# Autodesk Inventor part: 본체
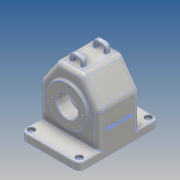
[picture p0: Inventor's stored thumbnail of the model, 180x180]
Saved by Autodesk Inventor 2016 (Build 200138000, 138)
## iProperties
Created: 2016-12
Part Number: 본체
Material: 알루미늄 6061
Document SubType Name: Modeling
Designer: Administrator
Density: 2.7 g/cm^3
Appearance: 알루미늄 - 평지
Mass: 1062.96 g
Surface Area: 1138.83 cm^2
Volume: 393.688 cm^3
Author: Administrator
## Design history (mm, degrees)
sketch "스케치1"
  geometry: L1 (45, -75)-(-45, -75); L2 (-55, -65)-(-55, 65); L3 (-45, 75)-(45, 75); L4 (55, 65)-(55, -65); L5 (55, -75)-(-55, 75); L6 (-55, -75)-(55, 75); A1 r 10 centre (-45, 65) between (-45, 75) and (-55, 65); A2 r 10 centre (45, 65) between (55, 65) and (45, 75); A3 r 10 centre (45, -65) between (45, -75) and (55, -65); A4 r 10 centre (-45, -65) between (-55, -65) and (-45, -75); 1 further point
  constraints: 12 end point, 8 point on circle, 8 point on line, 8 tangent, 4 centre point, 3 equal radius, 2 midpoint, 2 parallel, 1 horizontal, 1 perpendicular
  dimensions: "d0" = 110 distance of L5.end L6.end; "d1" = 150 distance of L6.start L5.end; "d2" = 10 radius of A1
extrude "돌출1" new body sketch "스케치1" distance "d3" = 15; taper "d4" = 0 deg
node "작업 평면1"
sketch "스케치2"
  geometry: L1 (55, 0)-(55, 15) reference; L2 (-55, 0)-(-55, 15) reference; L3 (45, 15)-(-45, 15) reference; L4 (55, 15)-(55, 80); L5 (55, 80)-(23.491, 125); L6 (23.491, 125)-(-23.491, 125); L7 (-23.491, 125)-(-55, 80); L8 (-55, 80)-(-55, 15); L9 (-45, 0)-(45, 0) reference; L10 (0, 125)-(0, 0)
  constraints: 12 end point, 2 perpendicular, 1 midpoint, 1 parallel, 1 vertical, 1 other
  dimensions: "d6" = 80 distance from line of L9 L4.end; "d7" = 125 distance between parallel lines of L9 L6; "d8" = 35 deg angle of L8 L7
extrude "돌출2" join sketch "스케치2" distance "d10" = 77; taper "d11" = 0 deg
node "작업 평면2"
sketch "스케치6"
  geometry: L1 (-55, 15)-(-55, 80) reference; L2 (-55, 80)-(-23.491, 125) reference; L3 (-23.491, 125)-(23.491, 125) reference; L4 (23.491, 125)-(55, 80) reference; L5 (55, 80)-(55, 15) reference; L6 (55, 0)-(55, 15) reference; L7 (-45, 0)-(45, 0) reference; L8 (-55, 0)-(-45, 0) reference; L9 (-55, 0)-(-55, 15) reference; L10 (45, 0)-(55, 0) reference; L11 (20.888, 120)-(-20.888, 120); L12 (-20.888, 120)-(-50, 78.424); L13 (-50, 78.424)-(-50, 15); L14 (-50, 15)-(-50, 0); L15 (50, 0)-(50, 15); L16 (50, 15)-(50, 78.424); L17 (50, 78.424)-(20.888, 120); L18 (50, 0)-(-50, 0); 1 further point
  constraints: 16 end point, 2 midpoint, 1 collinear, 3 other
  dimensions: "d30" = 5 distance between parallel lines of L3 L11
extrude "돌출3" cut sketch "스케치6" distance "d31" = 67; taper "d32" = 0 deg
sketch "스케치4"
  geometry: L1 (-43.5, 65)-(48.5, 65); L2 (-38.5, 102.5)-(-43.5, 102.5); L3 (-43.5, 102.5)-(-43.5, 65); L4 (38.5, 80)-(38.5, 125) reference; L5 (38.5, 96)-(48.5, 96); L6 (48.5, 96)-(48.5, 65); L7 (-38.5, 102.5)-(-38.5, 65); L8 (38.5, 96)-(38.5, 65); L9 (38.5, 15)-(38.5, 80) reference; L10 (-38.5, 80)-(-38.5, 125) reference; 1 further point
  constraints: 14 end point, 4 point on line, 3 horizontal, 3 perpendicular, 1 vertical alignment
  dimensions: "d13" = 65 vertical distance of L1.start point (0, 0); "d14" = 75 diameter of L2 L1; "d15" = 62 diameter of L5 L1; "d16" = 5 distance of L2.start L2.end; "d17" = 87 distance from line of L10 L5.end
revolve "회전1" sketch "스케치4" stored, may be unused: angle "d18" = 90 deg
sketch "스케치7"
  geometry: L1 (-33.5, 120)-(-33.5, 78.424) reference; L2 (-33.5, 78.424)-(-33.5, 0) reference; L3 (-33.5, 65)-(33.5, 65); L4 (33.5, 0)-(33.5, 78.424) reference; L5 (-19.5, 92)-(-19.5, 65); L6 (-43.5, 27.5)-(-43.5, 102.5) reference; L7 (-19.5, 92)-(-33.5, 106); 1 further point
  constraints: 6 end point, 4 point on line, 2 perpendicular
  dimensions: "d33" = 54 diameter of L5.start L3; "d34" = 130 diameter of point (0, 0) L3; "d36" = 24 distance between parallel lines of L6 L5; "d37" = 45 deg angle of L5 L7
revolve "회전3" sketch "스케치7" stored, may be unused: angle "d38" = 90 deg
hole "구멍1" diameter "d41" = 40; stored, may be unused: countersink angle "d45" = 90 deg, drill point angle "d47" = 118 deg; dims "d39" = 10, "d40" = 10, "d42" = 6, "d43" = 4, "d44" = 2, "d46" = 8
chamfer "모따기1" distance "d48" = 1; stored, may be unused: second distance "d49" = 2, angle "d50" = 45 deg
fillet "모깎기1" dims "d51" = 3
fillet "모깎기2" dims "d52" = 3
node "작업 평면3"
sketch "스케치8"
  geometry: L1 (12.5, 125)-(12.5, 132); L2 (4.5, 140)-(-4.5, 140); L3 (-12.5, 132)-(-12.5, 125); L4 (23.491, 125)-(-23.491, 125) reference; L5 (23.491, 125)-(-23.491, 125) reference; L6 (-45, 0)-(45, 0) reference; L7 (0, 125)-(0, 140); L8 (-7.5, 125)-(-7.5, 132); L9 (-4.5, 135)-(4.5, 135); L10 (7.5, 132)-(7.5, 125); L11 (7.5, 125)-(12.5, 125); L12 (-7.5, 125)-(-12.5, 125); L13 (47, 0)-(47, 77.478) reference; A1 r 8 centre (4.5, 132) between (12.5, 132) and (4.5, 140); A2 r 8 centre (-4.5, 132) between (-4.5, 140) and (-12.5, 132); A3 r 3 centre (-4.5, 132) between (-4.5, 135) and (-7.5, 132); A4 r 3 centre (4.5, 132) between (7.5, 132) and (4.5, 135); 3 further points
  constraints: 18 end point, 8 point on circle, 8 point on line, 5 perpendicular, 4 centre point, 4 tangent, 2 midpoint, 2 vertical, 1 collinear, 1 equal radius, 5 other
  dimensions: "d54" = 25 distance of point (12.5, 140) point (-12.5, 140); "d55" = 140 distance between parallel lines of L6 L2; "d56" = 8 radius of A1; "d57" = 5 distance between parallel lines of L2 L9
extrude "돌출4" join sketch "스케치8" distance "d60" = 8; taper "d61" = 0 deg
fillet "모깎기3" dims "d62" = 1
fillet "모깎기4" dims "d63" = 1
sketch "스케치9"
  geometry: C1 r 37.5 at (0, 0) reference; C2 r 21 at (0, 0) reference; A1 r 29 centre (0, 0) between (0, 29) and (0, -29); 3 further points
  constraints: 4 point on circle, 2 horizontal alignment, 2 vertical alignment, 1 centre point, 1 coincident
  dimensions: "d64" = 58 diameter of A1
hole "구멍2" sketch "스케치9" at (0, 29), (0, -29), (-29, 0), (29, 0) diameter "d65" = 2.459; stored, may be unused: countersink angle "d69" = 90 deg, drill point angle "d71" = 118 deg; dims "d66" = 6, "d67" = 4, "d68" = 2, "d70" = 8
sketch "스케치10"
  geometry: C1 r 31 at (0, 0) reference; C2 r 21 at (0, 0) reference; A1 r 26 centre (0, 0) between (-26, 0) and (26, 0); 3 further points
  constraints: 4 point on circle, 2 horizontal alignment, 2 vertical alignment, 1 centre point, 1 coincident
  dimensions: "d72" = 52 diameter of A1
hole "구멍3" sketch "스케치10" at (-26, 0), (26, 0), (0, -26), (0, 26) diameter "d73" = 2.459; stored, may be unused: countersink angle "d77" = 90 deg, drill point angle "d79" = 118 deg; dims "d74" = 6, "d75" = 4, "d76" = 2, "d78" = 8
sketch "스케치11"
  geometry: A1 r 10 centre (-45, -65) between (-55, -65) and (-45, -75) reference; A2 r 10 centre (45, -65) between (45, -75) and (55, -65) reference; A3 r 10 centre (-45, 65) between (-45, 75) and (-55, 65) reference; A4 r 10 centre (45, 65) between (55, 65) and (45, 75) reference; 5 further points
  constraints: 4 coincident
hole "구멍4" sketch "스케치11" at (-45, -65), (45, -65), (-45, 65), (45, 65) diameter "d80" = 5; stored, may be unused: countersink angle "d84" = 90 deg, drill point angle "d86" = 118 deg; dims "d81" = 6, "d82" = 12, "d83" = 5, "d85" = 8
fillet "모깎기5" dims "d87" = 10
fillet "모깎기6" dims "d88" = 8
fillet "모깎기7" dims "d89" = 3
node "작업 평면4"
sketch "스케치12" dims "d0" = 110, "d1" = 150, "d2" = 10
  geometry: L1 (-38.5, 76.847)-(-38.5, 18) reference; 3 further points
  constraints: 1 coincident, 1 other
  dimensions: "d91" = 45 distance of point (0, 0) point (0, 45); "d92" = 38.5 horizontal distance of L1.end point (0, 45)
feature "엠보싱1" sketch "스케치12" dims "d0" = 110, "d1" = 150, "d2" = 10, "d93" = 0.5, "d94" = 0
node "솔리드1"
mirror "대칭1"
other parameters: "d5" = -38.5, "d9" = 77, "d29" = -5, "d53" = -26
